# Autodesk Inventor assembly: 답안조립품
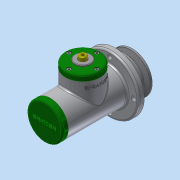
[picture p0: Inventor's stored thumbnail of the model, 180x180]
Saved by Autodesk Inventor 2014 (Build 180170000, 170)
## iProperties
Created: 2016-08
Part Number: 답안조립품
Document SubType Name: Assembly
Designer: 406-0014
Author: 406-0014
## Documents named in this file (25)
- C:\Users\406-0014\Desktop\답안조립품.iam
- C:\Users\406-0014\Desktop\본체.ipt
- C:\Users\406-0014\Desktop\V-벨트풀리.ipt
- C:\Users\406-0014\Desktop\너트 M10.ipt
- C:\Users\406-0014\Desktop\링크.ipt
- C:\Users\406-0014\Desktop\멈춤링 15 x 1.ipt
- C:\Users\406-0014\Desktop\멈춤링 35x1.6.ipt
- C:\Users\406-0014\Desktop\베어링 15 x 35 x 11.ipt
- C:\Users\406-0014\Desktop\볼트 M4 x 10.ipt
- C:\Users\406-0014\Desktop\볼트 M4 x 12.ipt
- C:\Users\406-0014\Desktop\부시1.ipt
- C:\Users\406-0014\Desktop\부시2.ipt
- C:\Users\406-0014\Desktop\분할핀 1.6 x 12.ipt
- C:\Users\406-0014\Desktop\사이드 커버.ipt
- 사이드 커버.ipt
- C:\Users\406-0014\Desktop\슬라이더.ipt
- C:\Users\406-0014\Desktop\오일 실 15 25 7.ipt
- C:\Users\406-0014\Desktop\와셔 4x16.ipt
- C:\Users\406-0014\Desktop\와셔 10x21.ipt
- C:\Users\406-0014\Desktop\클래스터 핀 6 x 24.ipt
- C:\Users\406-0014\Desktop\키 4 x 4 x 18.ipt
- C:\Users\406-0014\Desktop\탑 부시.ipt
- C:\Users\406-0014\Desktop\탑 커버.ipt
- 탑 커버.ipt
- C:\Users\406-0014\Desktop\편심축.ipt
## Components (6 placed, 3 different names)
1. V-벨트풀리:1 — 플러쉬:1
2. ISO 4017 M4 x 10:1
3. ISO 4762 M4 x 12:1
4. ISO 4762 M4 x 12:2
5. ISO 4762 M4 x 12:3
6. ISO 4762 M4 x 12:4
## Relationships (1: Flush 1)
- 플러쉬:1 [Flush]: V-벨트풀리:1
